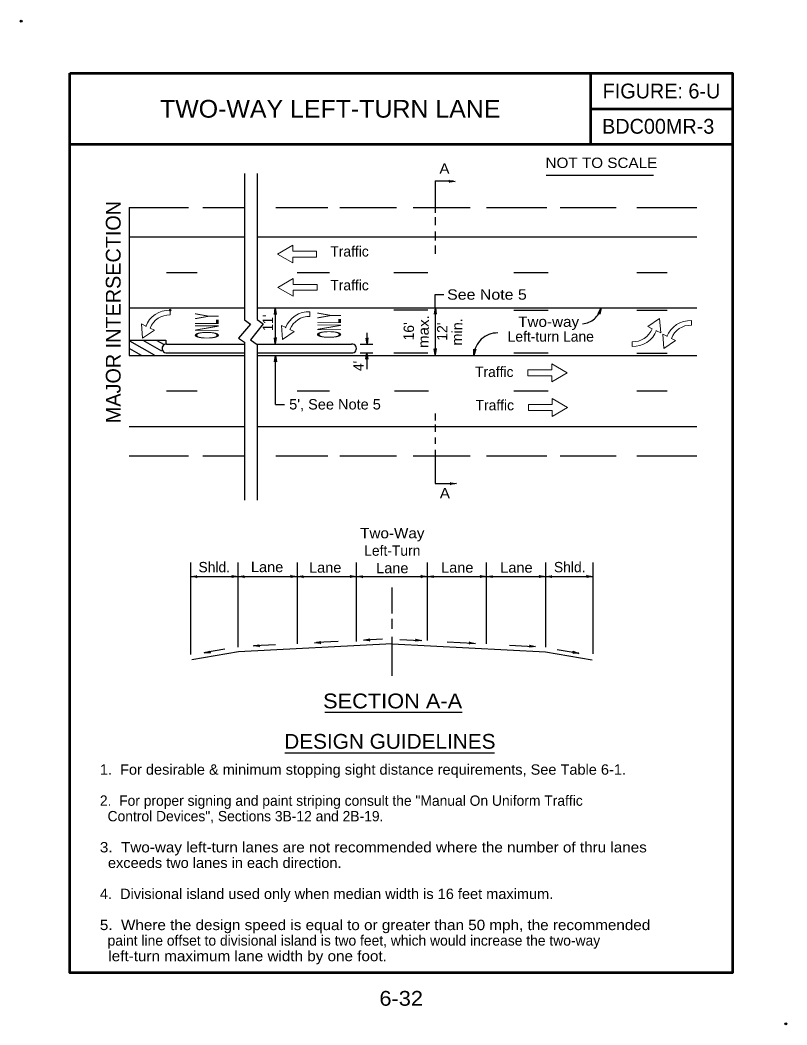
# Model space of a CAD drawing. Extents: x -6.896 to -6.221, y 4.889 to 5.773.
import ezdxf
from ezdxf.enums import TextEntityAlignment as Align

# ---------------------------------------------------------------- set-up
doc = ezdxf.new("R2010")
doc.units = 0
doc.header["$LTSCALE"] = 0.0036
doc.header["$PDMODE"] = 32
doc.header["$PDSIZE"] = 0.0018
doc.linetypes.add('LONG_DASHED', pattern=[7.5, 6, -1.5])
doc.layers.add('1', color=7, linetype='Continuous', lineweight=25)
doc.layers.add('60', color=7, linetype='Continuous', lineweight=13)

msp = doc.modelspace()

# ---------------------------------------------------------------- linework, layer by layer
at = {"layer": '1', "lineweight": 53}
for p, q in [((-6.393925, 5.726117), (-6.393925, 5.663617)), ((-6.393925, 5.694867), (-6.268925, 5.694867)), ((-6.852258, 5.663617), (-6.268925, 5.663617))]:
    msp.add_line(p, q, dxfattribs=at)
at = {"layer": '1'}
for p, q in [((-6.4331, 5.636408), (-6.3384, 5.636408)), ((-6.5306, 5.63135), (-6.514675, 5.63135)), ((-6.5306, 5.63135), (-6.5306, 5.6033)), ((-6.513017, 5.630992), (-6.518375, 5.6302)), ((-6.8002, 5.608067), (-6.747808, 5.608067)), ((-6.8002, 5.608067), (-6.8002, 5.477858)), ((-6.73535, 5.608067), (-6.698625, 5.608067)), ((-6.671083, 5.608067), (-6.625175, 5.608067)), ((-6.614675, 5.608067), (-6.564833, 5.608067)), ((-6.5502, 5.608067), (-6.499908, 5.608067)), ((-6.485475, 5.608067), (-6.43235, 5.608067)), ((-6.420542, 5.608067), (-6.37135, 5.608067)), ((-6.352992, 5.608067), (-6.3002, 5.608067)), ((-6.5306, 5.599358), (-6.5306, 5.592475)), ((-6.8002, 5.582025), (-6.698625, 5.582025)), ((-6.687475, 5.582025), (-6.3002, 5.582025)), ((-6.5306, 5.5869), (-6.5306, 5.579025)), ((-6.5306, 5.574433), (-6.5306, 5.567217)), ((-6.7673, 5.550775), (-6.740083, 5.550775)), ((-6.652267, 5.550775), (-6.623742, 5.550775)), ((-6.567, 5.550775), (-6.537158, 5.550775)), ((-6.461408, 5.550775), (-6.431225, 5.550775)), ((-6.353175, 5.550775), (-6.326292, 5.550775)), ((-6.8002, 5.519525), (-6.698625, 5.519525)), ((-6.687475, 5.519525), (-6.3002, 5.519525)), ((-6.671425, 5.519258), (-6.670633, 5.5139)), ((-6.671308, 5.4877), (-6.671308, 5.518892)), ((-6.5306, 5.519525), (-6.5306, 5.477858)), ((-6.530517, 5.519592), (-6.529725, 5.514233)), ((-6.384633, 5.519525), (-6.385683, 5.514217)), ((-6.567, 5.517925), (-6.537158, 5.517925)), ((-6.461408, 5.517592), (-6.431225, 5.517592)), ((-6.353175, 5.517592), (-6.326292, 5.517592)), ((-6.785425, 5.503675), (-6.78555, 5.503358)), ((-6.6623, 5.502383), (-6.662425, 5.502067)), ((-6.671467, 5.488058), (-6.672258, 5.493408)), ((-6.590675, 5.487725), (-6.591467, 5.493075)), ((-6.590675, 5.48765), (-6.590675, 5.497525)), ((-6.335833, 5.499525), (-6.335708, 5.499842)), ((-6.326508, 5.494633), (-6.326633, 5.494317)), ((-6.799917, 5.48385), (-6.789617, 5.4779)), ((-6.79975, 5.490733), (-6.778033, 5.478192)), ((-6.7881, 5.491233), (-6.771758, 5.4818)), ((-6.7758, 5.491067), (-6.769767, 5.487592)), ((-6.767217, 5.487733), (-6.698625, 5.487733)), ((-6.698625, 5.48945), (-6.698625, 5.487733)), ((-6.698625, 5.487783), (-6.698625, 5.350483)), ((-6.687908, 5.487733), (-6.604225, 5.487733)), ((-6.687475, 5.487617), (-6.687475, 5.350483)), ((-6.596833, 5.48765), (-6.585583, 5.48765)), ((-6.530725, 5.478383), (-6.531517, 5.483733)), ((-6.496542, 5.477933), (-6.496508, 5.483325)), ((-6.8002, 5.477858), (-6.698625, 5.477858)), ((-6.767217, 5.480025), (-6.698625, 5.480025)), ((-6.687475, 5.480025), (-6.604225, 5.480025)), ((-6.687475, 5.477858), (-6.3002, 5.477858)), ((-6.6712, 5.434742), (-6.6712, 5.477483)), ((-6.671158, 5.4776), (-6.670367, 5.472242)), ((-6.596833, 5.479942), (-6.585583, 5.479942)), ((-6.590725, 5.479892), (-6.589933, 5.474533)), ((-6.590675, 5.465758), (-6.590675, 5.479942)), ((-6.567, 5.480192), (-6.537158, 5.480192)), ((-6.461408, 5.480192), (-6.431225, 5.480192)), ((-6.353175, 5.479858), (-6.326292, 5.479858)), ((-6.7673, 5.446608), (-6.740083, 5.446608)), ((-6.652267, 5.446608), (-6.623742, 5.446608)), ((-6.56635, 5.446608), (-6.536508, 5.446608)), ((-6.461408, 5.446608), (-6.431225, 5.446608)), ((-6.353175, 5.446608), (-6.326292, 5.446608)), ((-6.6712, 5.434742), (-6.663375, 5.434742)), ((-6.5306, 5.426808), (-6.5306, 5.420567)), ((-6.8002, 5.415358), (-6.698625, 5.415358)), ((-6.687475, 5.415358), (-6.3002, 5.415358)), ((-6.5306, 5.416967), (-6.5306, 5.4104)), ((-6.5306, 5.405483), (-6.5306, 5.3999)), ((-6.5306, 5.39465), (-6.5306, 5.36495)), ((-6.8002, 5.389317), (-6.747808, 5.389317)), ((-6.73535, 5.389317), (-6.698625, 5.389317)), ((-6.671083, 5.389317), (-6.625175, 5.389317)), ((-6.614675, 5.389317), (-6.564833, 5.389317)), ((-6.5502, 5.389317), (-6.499908, 5.389317)), ((-6.485475, 5.389317), (-6.43235, 5.389317)), ((-6.420542, 5.389317), (-6.37135, 5.389317)), ((-6.352992, 5.389317), (-6.3002, 5.389317)), ((-6.5306, 5.36495), (-6.513325, 5.36495)), ((-6.512033, 5.364942), (-6.517383, 5.36415)), ((-6.746058, 5.2956), (-6.746058, 5.214525)), ((-6.704392, 5.2956), (-6.704392, 5.221092)), ((-6.652308, 5.2956), (-6.652308, 5.224008)), ((-6.600225, 5.2956), (-6.600225, 5.22615)), ((-6.537725, 5.2956), (-6.537725, 5.227017)), ((-6.485642, 5.2956), (-6.485642, 5.224008)), ((-6.433558, 5.2956), (-6.433558, 5.221092)), ((-6.391892, 5.2956), (-6.391892, 5.215175)), ((-6.746058, 5.283108), (-6.391892, 5.283108)), ((-6.745825, 5.28315), (-6.740467, 5.283942)), ((-6.704308, 5.2832), (-6.709667, 5.282408)), ((-6.704117, 5.28315), (-6.698758, 5.283942)), ((-6.65245, 5.28315), (-6.6578, 5.282358)), ((-6.652133, 5.2831), (-6.646783, 5.283892)), ((-6.600175, 5.283158), (-6.605533, 5.282367)), ((-6.599992, 5.28315), (-6.594633, 5.283942)), ((-6.537808, 5.28315), (-6.543167, 5.282358)), ((-6.537508, 5.28315), (-6.532158, 5.283942)), ((-6.485617, 5.28315), (-6.490967, 5.282358)), ((-6.485583, 5.283142), (-6.480225, 5.283933)), ((-6.4337, 5.2832), (-6.43905, 5.282408)), ((-6.433383, 5.28315), (-6.428033, 5.283942)), ((-6.391925, 5.283217), (-6.397283, 5.282425)), ((-6.568975, 5.273633), (-6.568975, 5.250808)), ((-6.568975, 5.246067), (-6.568975, 5.237025)), ((-6.593867, 5.227258), (-6.588558, 5.228325)), ((-6.577175, 5.2281), (-6.592808, 5.227275)), ((-6.568975, 5.230142), (-6.568975, 5.195683)), ((-6.561883, 5.227867), (-6.543642, 5.226908)), ((-6.542592, 5.226925), (-6.547975, 5.226408)), ((-6.73395, 5.215942), (-6.728808, 5.21765)), ((-6.715883, 5.219217), (-6.732758, 5.216233)), ((-6.691, 5.222092), (-6.6857, 5.223158)), ((-6.671208, 5.223158), (-6.689933, 5.222183)), ((-6.636917, 5.224892), (-6.631617, 5.225967)), ((-6.6161, 5.226058), (-6.635158, 5.225058)), ((-6.520133, 5.225683), (-6.497125, 5.224475)), ((-6.495242, 5.224342), (-6.500625, 5.223825)), ((-6.465242, 5.222808), (-6.4442, 5.2217)), ((-6.442283, 5.221642), (-6.447667, 5.221133)), ((-6.423142, 5.218992), (-6.405683, 5.215908)), ((-6.404208, 5.215617), (-6.409617, 5.215775)), ((-6.627817, 5.163783), (-6.50685, 5.163783)), ((-6.663075, 5.12795), (-6.478508, 5.12795))]:
    msp.add_line(p, q, dxfattribs=at)
at = {"layer": '1', "lineweight": 53}
msp.add_lwpolyline([(-6.852258, 5.726117), (-6.268925, 5.726117), (-6.268925, 4.93445), (-6.852258, 4.93445)], close=True, dxfattribs=at)
at = {"layer": '1'}
for points in [[(-6.698625, 5.637883), (-6.698625, 5.509142), (-6.693217, 5.5052), (-6.703708, 5.493058), (-6.698625, 5.48945)], [(-6.687475, 5.637883), (-6.687475, 5.509467), (-6.682075, 5.505525), (-6.693217, 5.491425), (-6.687475, 5.487483)], [(-6.517467, 5.630983), (-6.518508, 5.63185), (-6.512958, 5.630983)], [(-6.518383, 5.630225), (-6.517467, 5.630967), (-6.517467, 5.630983)], [(-6.5306, 5.519525), (-6.5306, 5.53135), (-6.5231, 5.53135)], [(-6.671417, 5.514808), (-6.672283, 5.513767), (-6.671417, 5.519317)], [(-6.530508, 5.515142), (-6.531375, 5.5141), (-6.530508, 5.51965)], [(-6.386117, 5.515333), (-6.387275, 5.514633), (-6.384608, 5.519592)], [(-6.670658, 5.513892), (-6.671392, 5.514808), (-6.671417, 5.514808)], [(-6.52975, 5.514225), (-6.530492, 5.515142), (-6.530508, 5.515142)], [(-6.385708, 5.514208), (-6.3861, 5.515325), (-6.386117, 5.515333)], [(-6.672242, 5.493425), (-6.6715, 5.492508), (-6.671475, 5.492508)], [(-6.671475, 5.492508), (-6.670617, 5.49355), (-6.671475, 5.487992)], [(-6.59145, 5.493092), (-6.590708, 5.492175), (-6.590683, 5.492175)], [(-6.590683, 5.492175), (-6.589825, 5.493217), (-6.590683, 5.487658)], [(-6.799917, 5.491233), (-6.767925, 5.491233), (-6.767925, 5.487525)], [(-6.5315, 5.483742), (-6.530758, 5.482825), (-6.530742, 5.482825)], [(-6.530742, 5.482825), (-6.529875, 5.483867), (-6.530742, 5.478317)], [(-6.495858, 5.482308), (-6.494867, 5.483217), (-6.496567, 5.477858)], [(-6.496483, 5.48335), (-6.495892, 5.482333), (-6.495858, 5.482308)], [(-6.671142, 5.47315), (-6.672008, 5.472108), (-6.671142, 5.477658)], [(-6.590717, 5.475442), (-6.591583, 5.4744), (-6.590717, 5.47995)], [(-6.589958, 5.474525), (-6.5907, 5.475442), (-6.590717, 5.475442)], [(-6.670383, 5.472233), (-6.671125, 5.47315), (-6.671142, 5.47315)], [(-6.516475, 5.364933), (-6.517517, 5.3658), (-6.511967, 5.364933)], [(-6.517392, 5.364175), (-6.516475, 5.364908), (-6.516475, 5.364933)], [(-6.741375, 5.283158), (-6.740333, 5.2823), (-6.745883, 5.283158)], [(-6.740458, 5.283925), (-6.741375, 5.283183), (-6.741375, 5.283158)], [(-6.708758, 5.283192), (-6.7098, 5.284058), (-6.70425, 5.283192)], [(-6.709675, 5.282433), (-6.708758, 5.283175), (-6.708758, 5.283192)], [(-6.699667, 5.283158), (-6.698625, 5.2823), (-6.704175, 5.283158)], [(-6.69875, 5.283925), (-6.699667, 5.283183), (-6.699667, 5.283158)], [(-6.656892, 5.283142), (-6.657933, 5.284008), (-6.652383, 5.283142)], [(-6.657808, 5.282383), (-6.656892, 5.283117), (-6.656892, 5.283142)], [(-6.647683, 5.283108), (-6.646642, 5.282242), (-6.6522, 5.283108)], [(-6.646767, 5.283867), (-6.647683, 5.283133), (-6.647683, 5.283108)], [(-6.604625, 5.28315), (-6.605667, 5.284017), (-6.600117, 5.28315)], [(-6.605542, 5.282392), (-6.604625, 5.283133), (-6.604625, 5.28315)], [(-6.595542, 5.283158), (-6.5945, 5.2823), (-6.60005, 5.283158)], [(-6.594625, 5.283925), (-6.595542, 5.283183), (-6.595542, 5.283158)], [(-6.542258, 5.283142), (-6.5433, 5.284008), (-6.53775, 5.283142)], [(-6.543175, 5.282383), (-6.542258, 5.283117), (-6.542258, 5.283142)], [(-6.533058, 5.283158), (-6.532017, 5.2823), (-6.537575, 5.283158)], [(-6.532142, 5.283925), (-6.533058, 5.283183), (-6.533058, 5.283158)], [(-6.490058, 5.283142), (-6.4911, 5.284008), (-6.48555, 5.283142)], [(-6.490975, 5.282383), (-6.490058, 5.283117), (-6.490058, 5.283142)], [(-6.481133, 5.28315), (-6.480092, 5.282283), (-6.485642, 5.28315)], [(-6.480217, 5.283908), (-6.481133, 5.283175), (-6.481133, 5.28315)], [(-6.438142, 5.283192), (-6.439183, 5.284058), (-6.433633, 5.283192)], [(-6.439058, 5.282433), (-6.438142, 5.283175), (-6.438142, 5.283192)], [(-6.428933, 5.283158), (-6.427892, 5.2823), (-6.43345, 5.283158)], [(-6.428017, 5.283925), (-6.428933, 5.283183), (-6.428933, 5.283158)], [(-6.396375, 5.2832), (-6.397417, 5.284067), (-6.391867, 5.2832)], [(-6.397292, 5.282442), (-6.396375, 5.283183), (-6.396375, 5.2832)], [(-6.589425, 5.227492), (-6.588342, 5.226692), (-6.593925, 5.227267)], [(-6.58855, 5.228308), (-6.589425, 5.227517), (-6.589425, 5.227492)], [(-6.547033, 5.227142), (-6.548033, 5.228058), (-6.542533, 5.226908)], [(-6.547992, 5.226433), (-6.547033, 5.227117), (-6.547033, 5.227142)], [(-6.568683, 5.224108), (-6.703917, 5.217025), (-6.74495, 5.209783)], [(-6.7288, 5.217633), (-6.729575, 5.216742), (-6.729575, 5.216725)], [(-6.686558, 5.222325), (-6.685475, 5.221525), (-6.691058, 5.2221)], [(-6.685683, 5.223142), (-6.686558, 5.22235), (-6.686558, 5.222325)], [(-6.632475, 5.225133), (-6.631392, 5.224325), (-6.636975, 5.2249)], [(-6.6316, 5.225942), (-6.632475, 5.22515), (-6.632475, 5.225133)], [(-6.568683, 5.224108), (-6.433458, 5.217025), (-6.392425, 5.209783)], [(-6.499675, 5.224558), (-6.500675, 5.225475), (-6.495175, 5.224325)], [(-6.500633, 5.22385), (-6.499675, 5.224533), (-6.499675, 5.224558)], [(-6.446717, 5.221858), (-6.447717, 5.222775), (-6.442217, 5.221633)], [(-6.447675, 5.22115), (-6.446717, 5.221842), (-6.446717, 5.221858)], [(-6.408592, 5.216383), (-6.409467, 5.217425), (-6.404142, 5.2156)], [(-6.729575, 5.216725), (-6.728392, 5.216058), (-6.734008, 5.215942)], [(-6.409625, 5.2158), (-6.408592, 5.216367), (-6.408592, 5.216383)]]:
    msp.add_lwpolyline(points, dxfattribs=at)
at = {"layer": '1', "linetype": 'LONG_DASHED'}
for centre, radius, start, end in [((-6.402379, 5.523888), 0.018274, 274.59331, 346.1877), ((-6.476023, 5.476995), 0.020558, 88.41937, 177.59309)]:
    msp.add_arc(centre, radius, start, end, dxfattribs=at)
at = {"layer": '1'}
for centre, start, end in [((-6.767217, 5.483879), 83.85097, 276.00097), ((-6.603821, 5.48391), 263.99903, 96.14903), ((-6.767217, 5.483879), 309.60656, 309.68796)]:
    msp.add_arc(centre, 0.00384, start, end, dxfattribs=at)
for p in [(-6.895233, 5.772), (-6.2219, 4.8895)]:
    msp.add_point(p, dxfattribs=at)
at = {"layer": '60'}
for p, q in [((-6.764017, 5.517533), (-6.764017, 5.513367)), ((-6.640892, 5.516242), (-6.640892, 5.512075)), ((-6.3051, 5.508492), (-6.3051, 5.504325))]:
    msp.add_line(p, q, dxfattribs=at)
for points in [[(-6.655992, 5.569592), (-6.635033, 5.569592), (-6.635033, 5.564383), (-6.655992, 5.564383), (-6.655992, 5.559175), (-6.669517, 5.566983), (-6.655992, 5.5748)], [(-6.6556, 5.540283), (-6.634642, 5.540283), (-6.634642, 5.535075), (-6.6556, 5.535075), (-6.6556, 5.529867), (-6.669133, 5.537683), (-6.6556, 5.545492)], [(-6.448967, 5.4599), (-6.448967, 5.465108), (-6.428008, 5.465108), (-6.428008, 5.470317), (-6.414475, 5.462508), (-6.428008, 5.454692), (-6.428008, 5.4599)], [(-6.448533, 5.434533), (-6.427575, 5.434533), (-6.427575, 5.439742), (-6.414042, 5.431933), (-6.427575, 5.424117), (-6.427575, 5.429325), (-6.448533, 5.429325)]]:
    msp.add_lwpolyline(points, close=True, dxfattribs=at)
for points in [[(-6.339592, 5.501325), (-6.343342, 5.503133), (-6.333033, 5.510183), (-6.332083, 5.497717), (-6.335833, 5.499525)], [(-6.781667, 5.501867), (-6.777917, 5.500067), (-6.788225, 5.493017), (-6.789175, 5.505483), (-6.785425, 5.503675)], [(-6.658542, 5.500575), (-6.654792, 5.498775), (-6.6651, 5.491725), (-6.66605, 5.504192), (-6.6623, 5.502383), (-6.662417, 5.502067)], [(-6.32275, 5.492825), (-6.319, 5.491025), (-6.329308, 5.483975), (-6.330258, 5.496442), (-6.326508, 5.494633), (-6.326625, 5.494317)], [(-6.357242, 5.485658), (-6.357242, 5.489825), (-6.357242, 5.489833)]]:
    msp.add_lwpolyline(points, dxfattribs=at)
for centre, radius, start, end in [((-6.764896, 5.495431), 0.022119, 87.73283, 158.99806), ((-6.764896, 5.495431), 0.017955, 87.19404, 158.99806), ((-6.641771, 5.49414), 0.022119, 87.73283, 158.99806), ((-6.641771, 5.49414), 0.017955, 87.19404, 158.99806), ((-6.35636, 5.507765), 0.017955, 267.19404, 338.99806), ((-6.305979, 5.48639), 0.022119, 87.73283, 158.99806), ((-6.305979, 5.48639), 0.017955, 87.19404, 158.99806), ((-6.35636, 5.507765), 0.022119, 267.73283, 338.99806)]:
    msp.add_arc(centre, radius, start, end, dxfattribs=at)
msp.add_point((-6.764017, 5.517533), dxfattribs=at)

# ---------------------------------------------------------------- texts
at = {"layer": '1'}
for s, height, p in [('FIGURE: 6-U', 0.01303, (-6.331425, 5.703975)), ('BDC00MR-3', 0.01303, (-6.334321, 5.672925)), ('Traffic', 0.009117, (-6.606067, 5.564825)), ('Traffic', 0.009117, (-6.606067, 5.53505)), ('Left-turn Lane', 0.009117, (-6.4289, 5.4899)), ('Traffic', 0.009117, (-6.478658, 5.458767)), ('Traffic', 0.009117, (-6.478192, 5.429458)), ('Left-Turn', 0.009117, (-6.568429, 5.301483)), ('Shld.', 0.009117, (-6.725175, 5.28695)), ('Shld.', 0.009117, (-6.412217, 5.28695))]:
    msp.add_text(s, height=height, dxfattribs=at).set_placement(p, align=Align.CENTER)
for s, height, width, p in [('TWO-WAY LEFT-TURN LANE', 0.01562, 1.05, (-6.623096, 5.68705)), ('See Note 5', 0.009117, 1.15, (-6.485092, 5.526833)), ('Two-way ', 0.009117, 1.1, (-6.4289, 5.502925)), ('Two-Way', 0.009117, 1.1, (-6.568425, 5.31685)), ('Lane', 0.009117, 1.05, (-6.678633, 5.28705)), ('Lane', 0.009117, 1.05, (-6.627483, 5.286583)), ('Lane', 0.009117, 1.05, (-6.568425, 5.286117)), ('Lane', 0.009117, 1.05, (-6.511225, 5.286583)), ('Lane', 0.009117, 1.05, (-6.459142, 5.286583)), ('6-32', 0.01303, 1.1, (-6.560592, 4.905458))]:
    msp.add_text(s, height=height, dxfattribs=dict(at, width=width)).set_placement(p, align=Align.CENTER)
for s, height, width, p in [('NOT TO SCALE', 0.009117, 1.1, (-6.433517, 5.642742)), ('A', 0.009117, 1.1, (-6.526975, 5.637633)), ("5', See Note 5", 0.009117, 1.05, (-6.659217, 5.4302)), ('A', 0.009117, 1.1, (-6.5266, 5.352017)), ('SECTION A-A', 0.01303, 1.1, (-6.629367, 5.167192)), ('DESIGN GUIDELINES', 0.01303, 1.05, (-6.663592, 5.131633)), ('1.  For desirable & minimum stopping sight distance requirements, See Table 6-1.', 0.009117, 1.05, (-6.825892, 5.108783)), ('3.  Two-way left-turn lanes are not recommended where the number of thru lanes', 0.009117, 1.1, (-6.825892, 5.040408)), ('  exceeds two lanes in each direction.', 0.009117, 1.05, (-6.825892, 5.026733)), ('4.  Divisional island used only when median width is 16 feet maximum.', 0.009117, 1.05, (-6.825892, 4.999383)), ('5.  Where the design speed is equal to or greater than 50 mph, the recommended', 0.009117, 1.1, (-6.825892, 4.972033)), ('  left-turn maximum lane width by one foot.', 0.009117, 1.1, (-6.825892, 4.944683))]:
    msp.add_text(s, height=height, dxfattribs=dict(at, width=width)).set_placement(p)
for s, height, p in [('MAJOR INTERSECTION', 0.01303, (-6.807608, 5.418192)), ("4'", 0.009117, (-6.5936, 5.463975))]:
    msp.add_text(s, height=height, rotation=90, dxfattribs=at).set_placement(p)
for s, height, rotation, width, p in [('ONLY', 0.02083, 90, 0.3, (-6.721258, 5.503696)), ('ONLY', 0.02083, 90, 0.3, (-6.613658, 5.504354)), ('max.', 0.009117, 88.978, 1.1, (-6.536361, 5.49866)), ('min.', 0.009117, 88.978, 1.05, (-6.506918, 5.498419))]:
    msp.add_text(s, height=height, rotation=rotation, dxfattribs=dict(at, width=width)).set_placement(p, align=Align.CENTER)
at = {"layer": '1', "width": 0.9}
msp.add_text("11'", height=0.009117, rotation=90, dxfattribs=at).set_placement((-6.673483, 5.499308))
at = {"layer": '1'}
for s, p in [("16'", (-6.549384, 5.498881)), ("12'", (-6.519943, 5.498644))]:
    msp.add_text(s, height=0.009117, rotation=88.978, dxfattribs=at).set_placement(p, align=Align.CENTER)
for s, p in [('2.  For proper signing and paint striping consult the "Manual On Uniform Traffic', (-6.825892, 5.081433)), ('  Control Devices", Sections 3B-12 and 2B-19.', (-6.825892, 5.067758)), ('  paint line offset to divisional island is two feet, which would increase the two-way', (-6.825892, 4.958358))]:
    msp.add_text(s, height=0.009117, dxfattribs=at).set_placement(p)

doc.saveas('drawing.dxf')
